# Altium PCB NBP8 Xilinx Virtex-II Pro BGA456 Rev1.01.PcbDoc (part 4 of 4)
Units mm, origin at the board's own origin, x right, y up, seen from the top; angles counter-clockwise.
Board outline 69 x 99.5 mm, 8 copper layers (Top Layer, InternalPlane1, InternalPlane2, MidLayer1, MidLayer2, MidLayer3, MidLayer4, Bottom Layer), stack 1.545 mm thick; 164 components, 314 nets, 1132 pads, 807 vias.
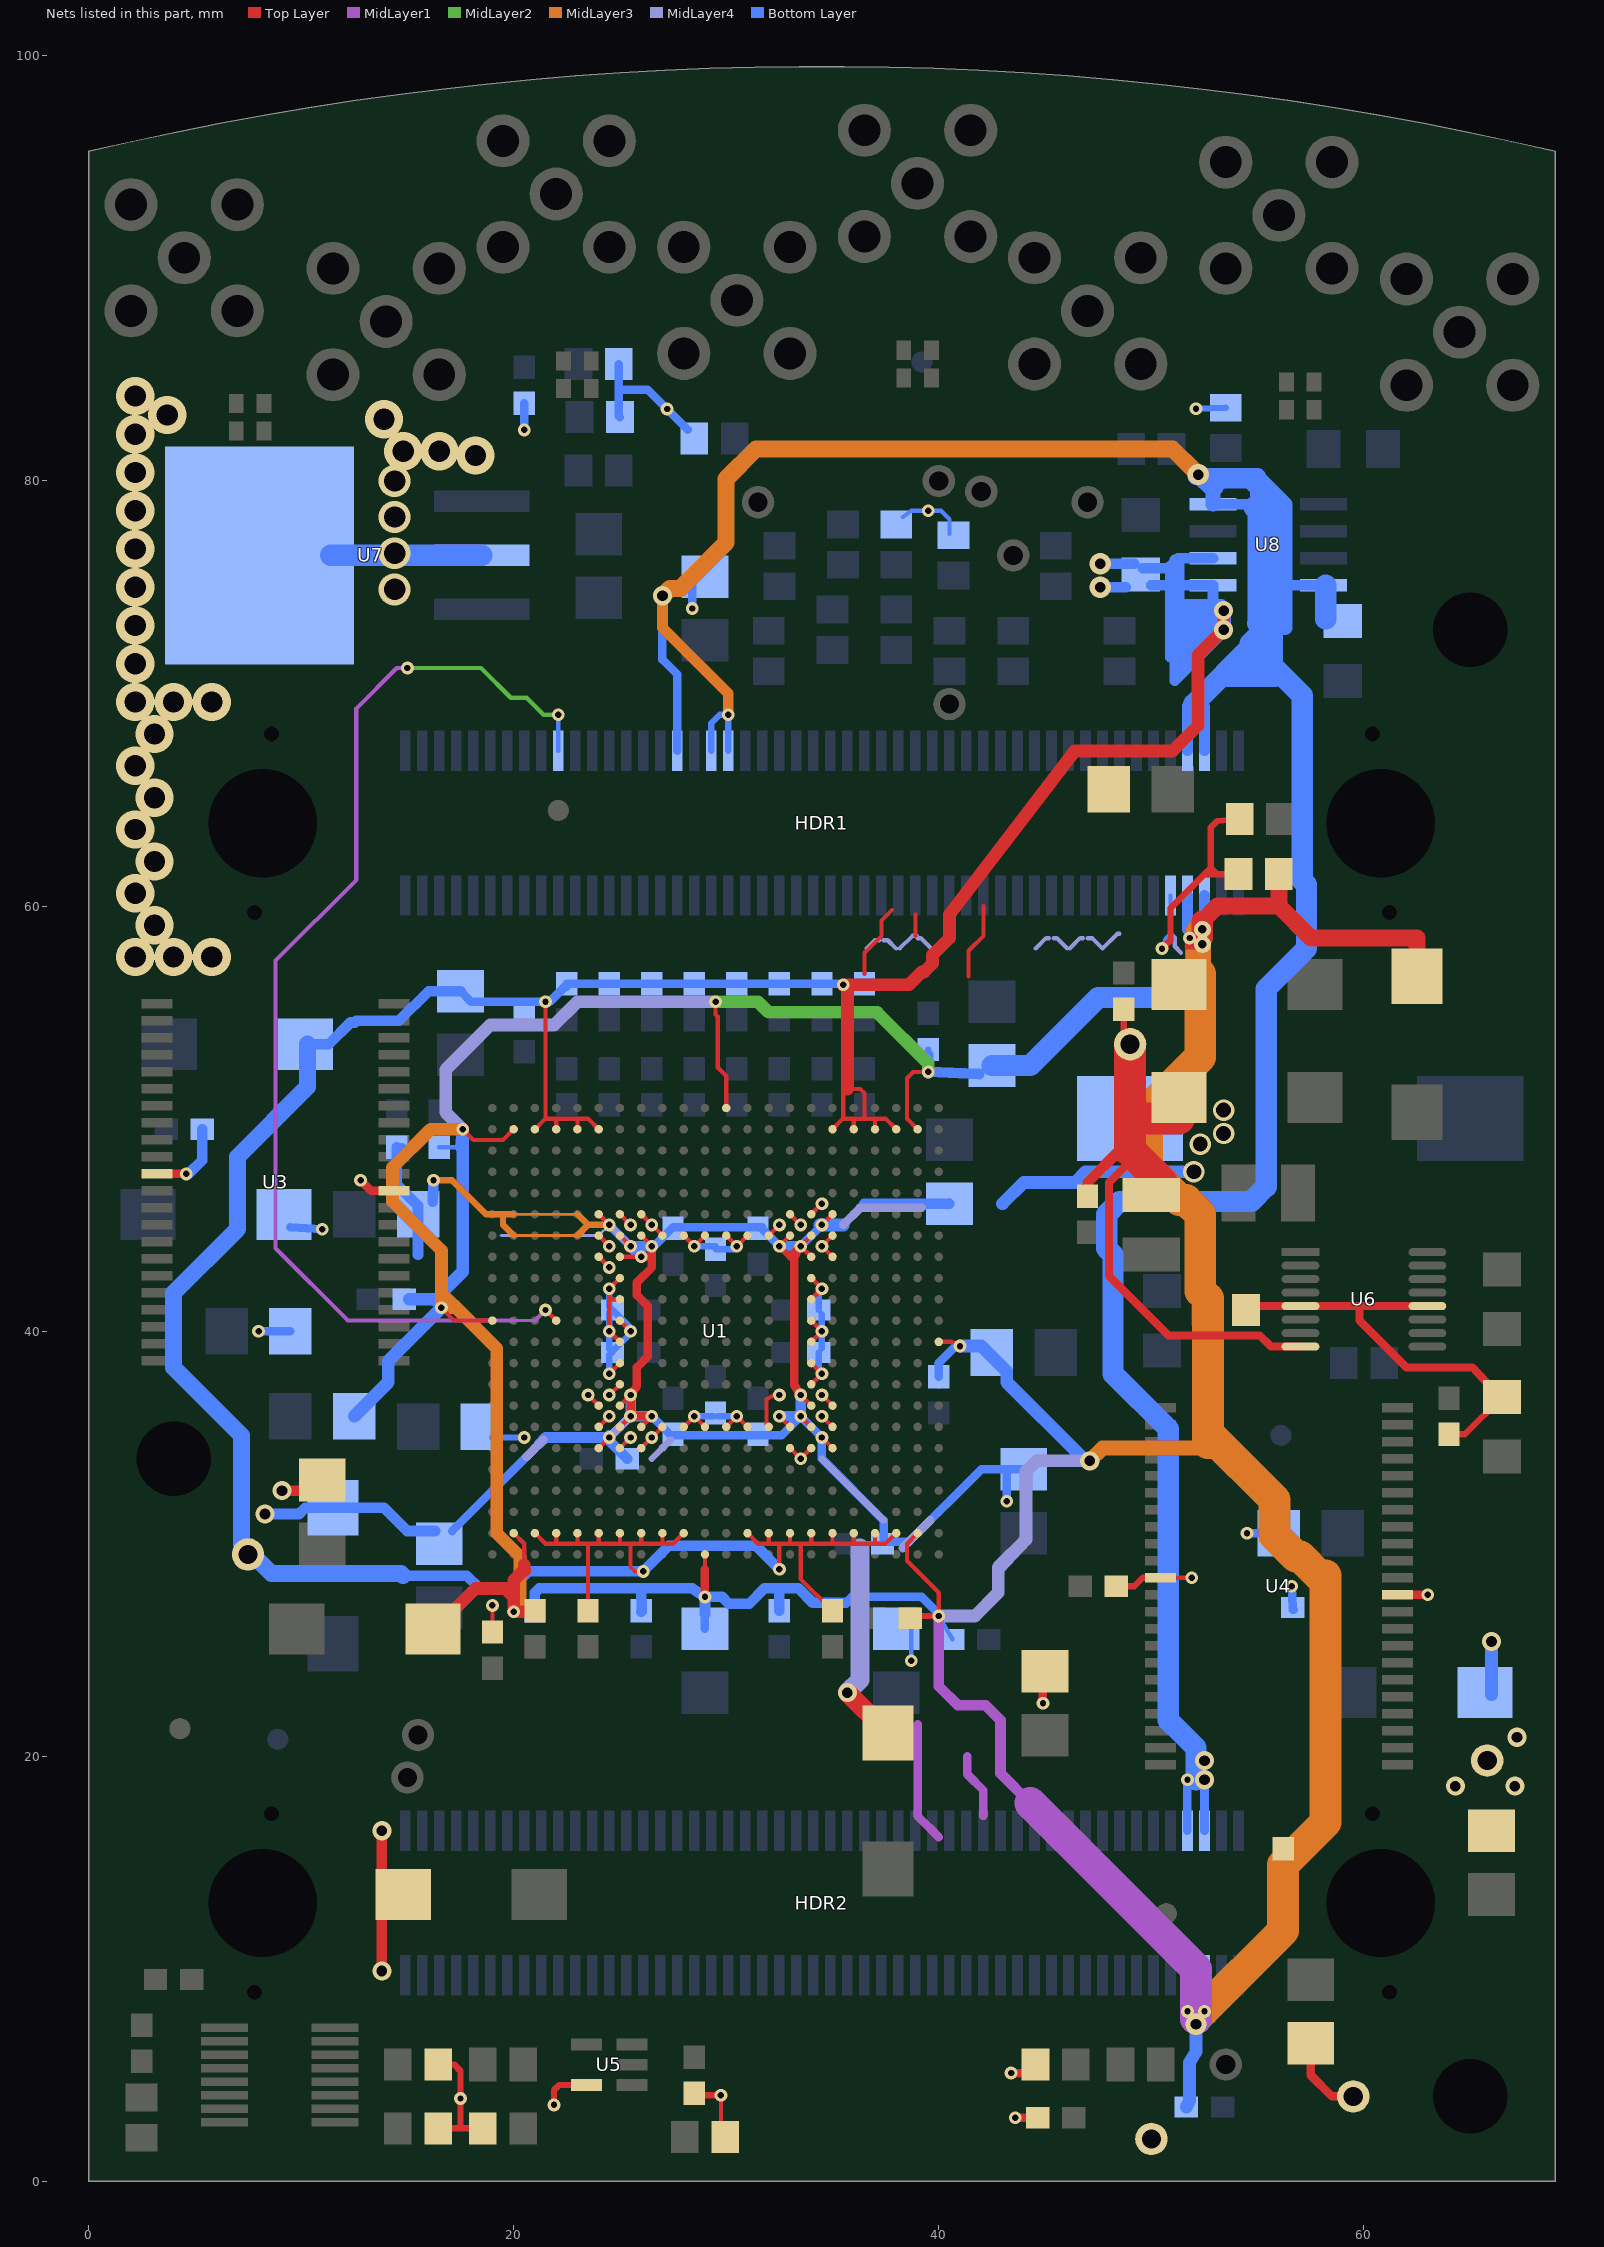
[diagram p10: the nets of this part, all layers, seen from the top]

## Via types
v1: diameter 0.6, hole 0.3, Top Layer to Bottom Layer, tented bottom, 695 vias
v2: diameter 0.9, hole 0.5, Top Layer to Bottom Layer, tented bottom, 45 vias
v3: diameter 1.8, hole 1, Top Layer to Bottom Layer, tented bottom, 26 vias
v4: diameter 1, hole 0.7, Top Layer to Bottom Layer, tented bottom, 17 vias
v5: diameter 1, hole 0.5, Top Layer to Bottom Layer, tented bottom, 15 vias
v6: diameter 1.5, hole 1, Top Layer to Bottom Layer, tented bottom, 4 vias
v7: diameter 0.8, hole 0.4, Top Layer to Bottom Layer, tented bottom, 3 vias
v8: diameter 0.9, hole 0.5, Top Layer to Bottom Layer, 2 vias

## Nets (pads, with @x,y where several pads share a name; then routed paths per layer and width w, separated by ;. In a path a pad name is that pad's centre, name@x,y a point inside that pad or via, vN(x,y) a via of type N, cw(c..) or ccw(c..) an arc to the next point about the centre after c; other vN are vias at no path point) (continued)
VCC: C9.1 C10.1 C11.1 C12.1 C13.1 C14.1 C15.1 C16.1 C17.1 C26.1 C27.1 C33.1 C35.1 C44.1 C45.1 C46.1 C47.1 C48.1 C49.1 C50.1 C56.1 C57.1 C58.1 C60.1 R10.1 R11.2 R12.1 R13.1 R14.2 R17.1 R19.2 R20.2 R23.1 R24.1 R27.2 TP11.1 U1.F7 U1.F8 U1.F15 U1.F16 U1.G6 U1.G9 U1.G10 U1.G11 U1.G12 U1.G13 U1.G14 U1.G17 U1.H6 U1.H17 U1.J7 U1.J16 U1.K7 U1.K16 U1.L7 U1.L16 U1.M7 U1.M16 U1.N7 U1.N16 U1.P7 U1.P16 U1.R6 U1.R17 U1.T6 U1.T9 U1.T10 U1.T11 U1.T12 U1.T13 U1.T14 U1.T17 U1.U7 U1.U8 U1.U15 U1.U16 U3.11 U3.33 U4.11 U4.33 U5.5 U7.2 U7.4 | length 118.6
  Top Layer w0.2: C33.1@19,25.85 v1(19,27.1) ; v1(23.5,37) U1.H17@24,36.5 ; U1.G17@24,35.5 v1(24.5,36) ; U1.R17@24,43.5 v1(24.5,43) ; U1.T17@24,44.5 v1(24.5,44) ; v1(24.5,37) U1.J16@25,37.5 ; v1(24.5,38) U1.K16@25,38.5 ; U1.L16@24.9,39.6 v1(24.5,40) 24.5,41.5 ; U1.F16@25,34.5 v1(25.5,35) ; U1.M16@25,40.4 25.1,40.4 v1(25.5,40) ; U1.N16@25,41.5 24.5,41.5 ; U1.P16@25,42.5 v1(24.5,42) 24.5,41.5 ; U1.U16@25,45.5 v1(25.5,45) ; U1.F15@26,34.5 v1(26.5,35) U1.G14@27,35.5 ; U1.U15@26,45.5 v1(26.5,45) U1.T14@27,44.5 ; U1.T13@28,44.5 v1(28.5,44) U1.T12@29,44.5 ; U1.G13@28.1,35.5 28.1,35.6 v1(28.5,36) U1.G12@29,35.5 ; R14.2@29.75,2.15 v1(29.75,4.05) ; U1.G11@30,35.5 v1(30.5,36) U1.G10@31,35.5 ; U1.T11@30,44.5 v1(30.5,44) U1.T10@31,44.5 ; U1.G9@32,35.5 31.9,35.6 31.9,36.8 32.25,37 v1(32.5,37) ; U1.T9@32,44.5 v1(32.5,45) ; U1.F8@33,34.5 v1(33.5,34) U1.F7@34,34.5 ; U1.U8@33,45.5 v1(33.5,45) ; U1.J7@34,37.5 v1(34.5,38) U1.K7@34,38.5 ; U1.L7@34,39.5 v1(34.5,40) U1.M7@34,40.5 ; U1.N7@34,41.5 v1(34.5,42) U1.P7@34,42.5 ; U1.U7@34,45.5 v1(34.5,46) ; v1(34.5,36) U1.G6@35,35.5 ; v1(34.5,37) U1.H6@35,36.5 ; U1.R6@35,43.5 v1(34.5,44) U1.T6@35,44.5 ; C44.1@44.9,24 44.95,24.05 C44.1@45,24.1 ; U4.11@50.5,28.4 v1(51.9,28.4)
  Top Layer w0.3: R17.1@16.45,2.5 17.5,2.5 ; R10.1@16.45,5.5 17.2,5.5 17.5,5.2 v1(17.5,3.9) 17.5,2.5 ; R20.2@18.55,2.5 17.5,2.5 ; v1(21.9,3.6) 21.9,4.3 22.141,4.541 U5.5@23.42,4.541 ; C35.1@28.5,4.05 v1(29.75,4.05) ; C27.1@48.35,28 49.2,28 49.6,28.4 U4.11@50.425,28.4
  Top Layer w0.4: U3.11@2.925,47.4 U3.11@3.225,47.4 4.4,47.4 v1(4.6,47.4) ; v1(12.8,47.1) 13.3,46.6 U3.33@14.375,46.6 U3.33@14.9,46.6 ; v1(43.4,5.1) 44.4,5.1 44.6,5.3 R19.2@44.6,5.5 ; v1(43.6,3) C13.1@44.65,3 C13.1@44.7,3 ; v1(44.9,22.5) C44.1@44.9,24 ; C60.1@57.5,6.5 57.5,5 58.5,4 TP11.1@59.5,4 ; U4.33@61.575,27.6 v1(63,27.6)
  Top Layer w0.5: v2(9.1,32.5) C46.1@11,32.5 ; v8(13.8,9.9) v8(13.8,16.5)
  Bottom Layer w0.2: R11.2@38.3,78.3 38.7,78.6 v1(39.5,78.6) 40.1,78.6 40.5,78.2 R13.1@40.5,77.5 ; v1(38.7,24.5) C48.1@38.7,26
  Bottom Layer w0.3: C50.1@19,35 v1(20.5,35) ; v1(24.5,38) 24.5,38.9 24.6,39 C14.1@24.65,39 24.5,39.15 v1(24.5,40) 24.5,40.9 24.6,41 C11.1@24.65,41 ; v1(24.5,42) 24.5,41.15 C11.1@24.65,41 ; C14.1@24.7,39.1 25.5,39.9 v1(25.5,40) 25.5,40.15 C11.1@24.65,41 ; v1(28.5,36) C12.1@29.4,36 ; v1(28.5,44) C10.1@29.5,44 ; C10.1@29.5,43.85 30.35,43.85 v1(30.5,44) ; C12.1@29.6,36 v1(30.5,36) ; C9.1@34.35,39 34.35,38.15 v1(34.5,38) ; C16.1@34.35,41 34.35,41.85 v1(34.5,42) ; C9.1@34.5,39.2 v1(34.5,40) C16.1@34.5,40.8 ; v1(52.1,83.4) R27.2@53.5,83.45
  Bottom Layer w0.4: v1(8,40) C47.1@9.5,40 ; C56.1@9.5,44.9 v1(11,44.8) ; v1(20.5,82.4) C17.1@20.5,83.65 ; R23.1@24.95,85.5 24.95,84.3 ; R24.1@25,83 24.95,83.05 24.95,84.3 ; R12.1@28.2,82.4 v1(27.218,83.382) 26.3,84.3 24.95,84.3 ; v1(28.4,74) C45.1@28.4,75.5 ; v1(54.5,30.5) C49.1@56,30.5 ; v1(56.6,28) 56.645,27 56.65,26.9 C15.1@56.7,26.9
  Bottom Layer w0.5: v1(4.6,47.4) 4.7,47.4 5.35,48.05 C26.1@5.35,49.5
  Bottom Layer w0.6: v2(66,25.4) 66,23 C57.1@66,22.9
  Bottom Layer w1: U7.4@11.4,76.5 14.4,76.5 U7.2@18.5,76.5
  other v3: 2.2,57.6 4,57.6 5.8,57.6 3.1,59.1 2.2,60.6 3.1,62.1 2.2,63.6 3.1,65.1 2.2,66.6 3.1,68.1 2.2,69.6 4,69.6 5.8,69.6 2.2,71.4 2.2,73.2 2.2,75 2.2,76.8 2.2,78.6 2.2,80.4 18.2,81.2 14.8,81.4 16.5,81.4 2.2,82.2 13.9,82.9 3.7,83.1 2.2,84
  other v6: 14.4,74.9 14.4,76.6 14.4,78.3 14.4,80
VCCAUX: C1.1 C2.1 C3.1 C4.1 C5.1 C6.1 C7.1 C28.1 C29.1 C30.1 C31.1 C36.1 C37.1 C38.1 C39.1 C51.1 C52.1 HDR1.93 HDR1.95 HDR2.93 HDR2.95 R15.1 TP14.1 U1.A12 U1.AA2 U1.AA21 U1.AB11 U1.B2 U1.B21 U1.L1 U1.M22 | length 312.9
  Top Layer w0.2: v1(16.6,41.1) 17.2,40.5 U1.M22@19,40.5 ; v1(17.6,49.5) 18.1,49 19.5,49 U1.AA21@20,49.5 ; 20,27.9 20,28.271 20,28.5 20.5,29 20.5,30 U1.B21@20,30.5 ; 29,28.8 U1.A12@29,29.5 ; v1(29.5,55.5) 29.5,54.9 29.6,54.8 29.6,52.4 30,52 U1.AB11@30,50.5 ; U1.B2@39,30.5 38.5,30 38.5,29.2 40,27.7 v1(40,26.6) ; U1.AA2@39,49.5 38.5,50 38.5,51.9 38.8,52.2 v1(39.5,52.2) ; U1.L1@40,39.5 40.6,39.5 v1@41,39.4
  Top Layer w0.3: C31.1@38.9,26.6 v1(40,26.6) ; 51.7,58.1 51.8,58.1 v7@52.4,58.1
  Top Layer w0.4: v1(29,27.5) 29,28.8
  Top Layer w0.6: C51.1@16.2,26 16.3,26 18.2,27.9 19.6,27.9 ; 20.5,29 20.5,28.771 ; 20.529,28.771 20.5,28.771 ; C30.1@20.7,26.8 v1(20,26.8) 20,27.5 ; 19.6,27.9 20,27.5 ; 19.6,27.9 20,27.9 ; 20,27.5 20,27.9 ; 20,27.9 20,28.271 20.5,28.771
  Top Layer w0.8: v7@52.4,59.3 53.1,60 56,60 ; R15.1@56,61.5 56,60 ; C52.1@62.5,56.7 62.5,58.5 57.5,58.5 56,60
  Top Layer w1: v7@52.4,58.5 v7(52.4,58.9) v7@52.4,59.3
  MidLayer1 w0.4: 39,21.5 39,17.2 40,16.2 ; 41.342,20 41.342,19.158 42.1,18.4 42.1,17.2
  MidLayer1 w0.5: v1(40,26.6) 40,23.3 40.9,22.4 42.2,22.4 42.9,21.7 42.9,19.2 44.3,17.8
  MidLayer1 w1.5: 44.3,17.8 52.1,10 52.1,8 v5@52.1,7.663
  MidLayer2 w0.6: v1(29.5,55.5) 31.5,55.5 32,55 37.1,55 39.5,52.6 v1(39.5,52.2)
  MidLayer3 w0.6: v1(17.6,49.5) 16.1,49.5 14.3,47.7 14.3,46.1 16.6,43.8 16.6,41.8 ; v1(20,26.8) 20.3,27.1 20.3,29.4 19.2,30.5 19.2,39.2 17.3,41.1 ; 16.6,41.8 v1(16.6,41.1) 17.3,41.1 ; 16.6,41.8 16.95,41.45 17.3,41.1
  MidLayer3 w0.7: v2(47.1,33.9) 47.7,34.5 52.3,34.5
  MidLayer3 w1.2: v7@52.2,58.8 52.2,58.5 52.2,58.2 52.2,56.9 52.3,56.8
  MidLayer3 w1.5: v5@52.1,7.7 52.45,8.05 56.2,11.8 56.2,14.9 58.2,16.9 58.2,28.5 57.9,28.5 57,29.4 56.8,29.4 55.8,30.4 55.8,32.069 52.669,35.2 ; 52.3,56.8 52.3,52.9 49.8,50.4 49.8,47.7 51.325,46.175 51.625,46.175 52.3,45.5 52.3,41.9 52.669,41.531 52.669,35.2 ; 52.669,34.731 52.669,35.2
  MidLayer4 w0.6: v1(17.6,49.5) 16.8,50.3 16.8,52.3 18.9,54.4 21.9,54.4 23,55.5 v1(29.5,55.5) ; v1(40,26.6) 41.7,26.6 42.8,27.7 42.8,28.8 44.1,30.2 ; 42.8,28.9 44.1,30.2 ; v2(47.1,33.9) 44.6,33.9 44.1,33.4 44.1,30.2
  Bottom Layer w0.2: C4.1@16.5,48.65 17.35,48.65 17.563,48.863 17.6,48.9 v1(17.6,49.5) v1@17.6,49.6 ; v1(20,26.8) 20.95,26.8 C1.1@21,26.85 ; v1(40,26.6) C2.1@40.65,25.5 ; HDR2.93@51.7,9.6 HDR2.93@51.7,9.7
  Bottom Layer w0.3: v1(39.5,52.2) C5.1@39.5,53.25
  Bottom Layer w0.38: C29.1@15.1,41.5 16.1,41.5 v1(16.6,41.1) ; v1(41,39.3) C39.1@41.8,39.3
  Bottom Layer w0.4: C37.1@29,26 v1(29,27.5) ; 35.617,27.217 35.9,27.5 39.2,27.5 40,26.7 v1(40,26.6) ; C7.1@40,37.85 40,38.5 40.8,39.3 v1(41,39.3) ; HDR2.93@51.7,9.6 v1(51.7,8) ; HDR2.95@52.5,9.7 v1(52.5,8) ; v1(51.7,8) 52.1,8 v1(52.5,8) ; v1(51.7,8) 51.7,7.8 v5(52.1,7.4) 52.5,7.8 v1(52.5,8)
  Bottom Layer w0.5: v1(20,26.8) 20.05,26.85 C1.1@21,26.85 21,27.7 21.2,27.9 26,27.9 ; C3.1@26,26.8 26.025,26.825 26.024,26.851 26,27.9 ; C37.1@29,26.7 v1(29,27.5) ; C6.1@32.5,26.85 32.5,27.9 ; 35.617,27.217 34.083,27.217 33.4,27.9 32.5,27.9 ; C5.1@39.5,53 v1(39.5,52.2) C38.1@41.9,52.1 ; 51.7,58.9 HDR1.93@51.7,60.5 ; v7@52.5,58.9 HDR1.95@52.5,60.5 ; 26,27.9 28.4,27.9 v1(29,27.5) ; v1(29,27.5) 29.8,27.5 30.114,27.186 31.086,27.186 31.8,27.9 32.5,27.9
  Bottom Layer w0.6: C36.1@12.5,36 14.1,37.6 14.1,38.6 v1(16.6,41.1) 16.6,41.5 ; C29.1@15.1,41.5 16.1,41.5 16.6,41.5 ; 17.55,48.65 17.563,48.863 v1(17.6,49.5) 17.6,48.9 17.6,42.8 16.6,41.8 16.6,41.5 ; v1(41,39.3) 42,39.3 42.4,38.9 43.2,38.1 43.2,37.6 46.7,34.1 v2(47.1,33.9) ; C28.1@51.65,3.5 51.8,3.8 51.8,5.6 52.1,6.1 v5(52.1,7.4)
  Bottom Layer w1: C38.1@42.5,52.5 44.3,52.5 47.5,55.7 50.9,55.7 52.1,56.9 52.1,58.2 v1@52.1,58.5
  other v1: 51.8,58.5
  other v7: 52.4,58.2
VCCIN: C76.1 C88.1 C93.2 HDR1.34 HDR1.38 HDR1.40 HDR1.94 HDR1.96 HDR2.94 HDR2.96 TP13.1 U8.4 U8.8 | length 182.7
  MidLayer3 w0.5: v2(27,74.6) 27,73.1 30.1,70 v1(30.1,69)
  MidLayer3 w0.8: v2(27,74.6) 27.351,74.951 27.851,74.951 30,77.1 30,80.1 31.4,81.5 51,81.5 v5@52,80.5
  Bottom Layer w0.3: HDR1.38@29.3,67.3 29.3,68.6 29.7,69 v1(30.1,69) HDR1.40@30.1,67.3 ; v1(51.7,18.9) 52.1,18.9 v2(52.5,18.9)
  Bottom Layer w0.4: v2(27,74.6) 27,71.6 27.7,70.9 HDR1.34@27.7,67.3 ; HDR2.94@51.7,16.5 v1(51.7,18.9) ; HDR2.96@52.5,16.5 v2(52.5,18.9)
  Bottom Layer w0.5: HDR1.94@51.7,67.3 51.7,69.4 52.089,69.789 ; HDR1.96@52.5,67.3 52.5,69.377 52.189,69.689 52.089,69.789 ; U8.8@52.9,78.905 54.695,78.905 55.5,78.1 55.5,74.1 55.5,73.2 54.653,72.353 52.089,69.789 ; 55.6,74.7 55.7,74.8 55.9,75 55.9,75.095 ; 55.6,75.6 55.7,75.5 56,75.2 ; 55.805,75.095 55.9,75.095 ; U8.4@58.2,75.095 U8.4@58.1,75.095 56.3,75.095 55.9,75.095
  Bottom Layer w0.7: U8.8@52.9,78.905 52.9,79.6 53,79.7 53.3,80 54.6,80 55,79.6 ; 54.4,80.2 55,80.2 56.3,78.9 56.3,78.2 ; 55,78.7 55,79.5 ; 55,80 55,79.6 ; 56.3,73.1 56.3,75.095 56.3,78.2 ; 55,79.5 55,79.6 ; 55,79.5 56.3,78.2
  Bottom Layer w0.8: v5@52.1,80.2 52.2,80.2 v5@52.3,80.2 ; v5(52.2,80.3) v5@52.3,80.2 ; 55,80.2 v5@52.5,80.2 ; v5@52.3,80.2 52.8,79.7 53,79.7 v5@52.5,80.2 ; v5@52.3,80.2 v5@52.5,80.2
  Bottom Layer w1: 52,69.5 52.189,69.689 54.653,72.153 54.653,72.353 57.1,69.905 57.1,61.2 57.3,61 57.3,58 55.4,56.1 55.4,46.8 54.7,46.1 48.5,46.1 47.9,45.5 47.9,43.9 48.2,43.6 48.2,38 50.8,35.4 50.8,21.7 52.1,20.4 52.1,19.8 v2@52.1,18.9 ; 53.6,70.8 55.8,70.8 55.2,71.4 54.5,71.4 ; 54.741,72.441 55.5,73.2 55.7,73.4 ; 54.836,78.764 55.5,78.1 55.7,77.9 55.7,75.5 55.7,74.8 55.7,73.4 ; 55,73.3 55.013,73.313 55.013,73.713 ; 55.013,78.587 55.013,73.713 ; 55.5,74.1 55.4,74.1 55.013,73.713 ; 55.7,71.459 55.7,73.4 ; C93.2@58.2,73.5 U8.4@58.2,75.095
  other v2: 64.3,18.6 67.1,18.6 52.5,19.8 67.2,20.9
VCCINT: C18.1 C19.1 C20.1 C21.1 C22.1 C23.1 C24.1 C25.1 C34.1 C40.1 C41.1 C42.1 C43.1 C53.1 C54.1 C55.1 C61.1 C62.2 L1.2 TP10.1 U1.F6 U1.F17 U1.G7 U1.G8 U1.G15 U1.G16 U1.H7 U1.H16 U1.R7 U1.R16 U1.T7 U1.T8 U1.T15 U1.T16 U1.U6 U1.U17 U6.8 | length 207.5
  Top Layer w0.2: U1.F17@24,34.5 v1(24.5,35) ; U1.U17@24,45.5 v1(24.5,45) ; U1.H16@25,36.5 v1(25.5,37) ; U1.R16@25,43.5 v1(26,43.5) ; U1.T16@25,44.5 v1(25.5,44) ; U1.G16@25.1,35.5 U1.G16@25,35.5 v1(25.5,36) ; U1.G15@26,35.5 v1(26.5,36) ; U1.T15@26,44.5 v1(26.5,44) ; v1(32.5,36) U1.G8@33,35.5 ; v1(32.5,44) U1.T8@33,44.5 ; v1(33.5,36) U1.G7@34,35.5 ; v1(33.5,37) U1.H7@34,36.5 ; U1.R7@34,43.5 v1(33.5,44) U1.T7@34,44.5 ; v1(34.5,35) U1.F6@35,34.5 ; v1(34.5,45) U1.U6@35,45.5 ; 55.6,39.3 55.622,39.278
  Top Layer w0.3: v1(32.5,44) 32.984,43.516 ; 32.984,43.484 32.984,43.516 ; C22.1@48.7,55.15 48.7,53.9 TP10.1@49,53.5 ; 32.984,43.516 33.468,44 v1(33.5,44) 33.2,43.3 32.984,43.516
  Top Layer w0.38: 48.8,47.8 48,47 48,42.6 50.8,39.8 55.1,39.8 55.6,39.3 ; 55.622,39.278 U6.8@57.015,39.278
  Top Layer w0.4: v1(26,43.5) 26.5,43.5 ; v1(26.5,36) v1(25.5,36) v1(25.5,37) 25.8,37.4 25.8,38.3 26.3,38.8 26.3,41.2 25.8,41.7 25.8,42.3 26.5,43 26.5,43.5 ; v1(26.5,44) 26.5,43.5 ; v1(33.5,37) 33.2,37.468 33.2,43.3 33.2,43.7 v1(33.5,44)
  Top Layer w0.5: C25.1@47,46.35 47,47 48.5,48.5
  Top Layer w0.9: v2(35.7,23) 37.5,21.2 37.5,21.1 C53.1@37.5,21
  Top Layer w1.5: TP10.1@49,53.5 49,50.5 ; C62.2@50.5,46.5 50.5,47 49,48.5 49,50.5 ; C61.1@51.3,50 49.5,50 49,50.5
  MidLayer3 w0.127: 20,44.5 23,44.5 ; 20,45.5 23,45.5
  MidLayer3 w0.3: v1(16.229,47.1) 17.1,47.1 18.7,45.5 19.5,45.5 ; 20,44.5 19.5,45 19.5,45.5 ; 20,45.5 19.5,45.5 ; 23,44.5 23.5,45 ; 23,45.5 23.5,45 ; v1(24.5,45) 23.5,45
  MidLayer4 w0.127: 19.4,44.5 23.4,44.5 24,44.5 v1(24.5,45) 23.474,45 22.974,45.5 19.4,45.5
  MidLayer4 w0.2: 21.403,34.811 21.403,34.903 21.408,34.908 ; 36.5,30 37.5,30 ; 36.607,58 37.001,58.394 37.2,58.394 ; 37.4,58.394 37.599,58.394 37.993,58 ; 38.158,58 38.758,58.6 38.958,58.6 ; 39.012,58.492 39.149,58.492 39.642,58 ; 44.558,58 45.051,58.492 45.188,58.492 ; 45.412,58.492 45.549,58.492 46.042,58 ; 46.158,58 46.651,58.492 46.788,58.492 ; 47.012,58.492 47.214,58.492 47.706,58 48.407,58.7 48.5,58.7 ; 51,58.625 51.1,58.524 51.1,58.107 51.4,57.807
  MidLayer4 w0.3: v1(24.5,45) v1(25.5,44) ; 26.499,34.001 27.401,34.903 ; 34.5,34 37.403,31.097
  MidLayer4 w0.4: 20.597,34.097 21.403,34.903 ; v1(24.5,35) v1(25.5,36) ; 35.5,45 36.265,45.764 ; 36.275,45.8 39.2,45.8 ; 38.3,29.8 39.6,31.1
  MidLayer4 w0.9: v2(35.7,23) 36.3,23.6 36.3,29.8
  Bottom Layer w0.3: v1(26.5,44) v1@26.6,44
  Bottom Layer w0.4: C34.1@14.5,48.65 C34.1@14.75,48.65 ; C42.1@17.1,30.6 21.2,34.7 ; v1(24.5,35) v1(25.5,36) ; v1(24.5,45) v1(25.5,44) ; v1(26.5,36) 27.4,35.1 27.5,35.1 31.5,35.1 32.6,35.1 v1(33.5,36) v1(34.5,35) 34.5,34 37.4,31.1 37.4,30.1 38.6,30.1 42,33.5 C40.1@44,33.5 ; v1@26.6,44 27.475,44.875 27.5,44.9 31.5,44.9 C18.1@31.6,44.9 ; C18.1@31.7,44.9 C18.1@31.6,44.9 ; v1(32.5,44) C18.1@31.6,44.9 ; v1(33.5,44) v1(34.5,45) 35.5,45 36.5,46 ; C43.1@40.487,46.072 C43.1@40.499,46.072 ; v1(43.2,32) C40.1@43.2,33.4
  Bottom Layer w0.5: v2(8.3,31.4) 9.9,31.4 10.2,31.7 C54.1@11.5,31.7 13.9,31.7 15,30.6 C42.1@16.3,30.6 ; C34.1@14.5,48.65 14.5,46.9 15.5,45.9 C41.1@15.5,45.5 15.5,43.6 ; C41.1@16.2,46.1 v1(16.229,47.1) ; 21.2,34.7 21.5,35 24.4,35 24.45,35.05 24.5,35.1 v1(24.5,35) 24.5,34.85 C24.1@25.35,34 ; v1(25.5,37) v1(25.5,36) v1(26.5,36) ; v1(26,43.5) v1(25.5,44) 26,44 v1(26.5,44) ; v1(32.5,36) v1(33.5,36) v1(33.5,37) ; v1(32.5,44) v1(33.5,44) ; 36.5,46 C43.1@40.5,46
  Bottom Layer w0.6: v1@34.4,45 v1(34.5,45) 35.5,45 ; 43,46 44,47 46.4,47 46.9,47.5 v4(52,47.5)
  other v4: 52.3,48.8 53.4,49.3 53.4,50.4
VCCRIO: C77.1 C78.1 C79.1 C89.1 C90.1 C91.1 C92.2 L2.2 L3.2 L4.2 L5.2 L6.2 L7.2 L8.2 L9.2 TP12.1 U1.AA3 U1.AA4 U1.AA5 U1.AA6 U1.AA17 U1.AA18 U1.AA19 U1.AA20 U1.B3 U1.B4 U1.B5 U1.B6 U1.B7 U1.B8 U1.B9 U1.B10 U1.B13 U1.B14 U1.B15 U1.B16 U1.B17 U1.B18 U1.B19 U1.B20 U8.5 U8.6 | length 223.1
  Top Layer w0.2: U1.B20@21,30.5 21.5,30 23.5,30 ; U1.AA20@21,49.5 21.5,50 ; v1(21.5,55.5) 21.5,50 ; 22,30 U1.B19@22,30.5 ; U1.AA19@22,49.5 22,50 ; 23,30 U1.B18@23,30.5 ; U1.AA18@23,49.5 23,50 ; C78.1@23.5,26.85 23.5,30 ; 24,30 U1.B17@24,30.5 ; U1.AA17@24,49.5 23.5,50 23,50 ; 25,30 U1.B16@25,30.5 ; 26,30 U1.B15@26,30.5 ; v1(26.1,28.7) 25.7,28.7 25.5,28.9 25.5,30 ; 27,30 U1.B14@27,30.5 ; U1.B13@28,30.5 27.5,30 25.5,30 ; U1.B10@31,30.5 31.5,30 32,30 ; U1.B9@32,30.5 32,30 ; v1(32.5,28.8) 32.5,30 ; U1.B8@33,30.5 33,30 ; U1.B7@34,30.5 34,30 ; C79.1@35,26.85 33.5,28.35 33.5,30 ; U1.B6@35,30.5 35,30 ; U1.AA6@35,49.5 35.5,50 ; v1(35.5,56.3) 35.5,51.4 ; 36,30 U1.B5@36,30.5 ; U1.AA5@36,49.5 36,50 ; 36.5,56.8 36.5,57.8 37.3,58.6 37.3,59.317 37.8,59.817 ; 37,30 U1.B4@37,30.5 ; U1.AA4@37,49.5 37,50 ; U1.B3@38,30.5 37.5,30 35,30 ; U1.AA3@38,49.5 37.5,50 37,50 ; 38.9,58.6 38.9,59.6 ; 41.4,56.7 41.4,57.9 42.1,58.6 42.1,60 ; 21.5,50 23,50 ; 23.5,30 25.5,30 ; 32,30 32.5,30 ; 32.5,30 33,30 ; 33,30 33.5,30 ; 33.5,30 34,30 ; 34,30 35,30 ; 35.5,50 36,50 ; 35.5,50 35.5,51.4 ; 35.5,51.4 35.7,51.4 36.3,51.4 36.5,51.2 36.5,50 ; 36,50 36.5,50 ; 36.5,50 37,50
  Top Layer w0.6: 35.7,51.4 35.7,56.1 v1(35.5,56.3) 38.6,56.3 39.2,56.9 39.3,56.9 39.7,57.3 39.7,57.7 40.5,58.5 40.5,59.6 46.4,67.3 51,67.3 52.2,68.5 52.2,71.8 v2(53.4,73) v2(53.4,73.9)
  Bottom Layer w0.4: C89.1@17.5,56 18,55.5 20.5,55.5 v1(21.5,55.5) 21.7,55.5 L2.2@22.5,56.3 ; L2.2@22.5,56.2 L2.2@22.5,56.3 ; L8.2@36.5,56.35 35.5,56.35 L9.2@34.5,56.35 L7.2@32.5,56.35 L6.2@30.5,56.35 L4.2@28.5,56.35 L5.2@26.5,56.35 L3.2@24.5,56.35 L2.2@22.5,56.35 L2.2@22.5,56.3
  Bottom Layer w0.5: C91.1@10.2,53.5 10.3,53.5 11.3,53.5 12.323,54.523 12.523,54.523 12.6,54.6 14.6,54.6 16,56 C89.1@17.5,56 ; 14.8,28.5 17.8,28.5 18.4,27.9 19.9,27.9 20.7,28.7 v1(26.1,28.7) 27.3,29.9 31.4,29.9 v1(32.5,28.8) ; v5(47.6,75) C92.2@48.8,75 ; v5(47.6,76.1) C92.2@49.2,76.1 ; C92.2@49.6,75.9 50.8,75.9 50.9,76 ; C92.2@50,75.1 50.005,75.095 50.9,75.095 ; 51.1,76.3 51.1,76.2 ; U8.6@52.9,76.365 51.265,76.365 51.1,76.2 ; 50.9,75.095 50.9,71.7 51.1,71.9 ; 50.9,75.095 50.9,76 ; 50.9,75.095 51.1,75.095 ; 50.9,76 51,76.1 ; 51,76.1 51.1,76.1 ; 51,76.1 51.1,76.2 ; 51.1,71.9 51.4,72.2 ; 51.1,71.9 51.1,70.6 53.45,72.95 53.5,73 53.5,73.9 53.5,74 53.3,74.2 52.9,74.2 ; 51.1,71.9 51.1,73.9 ; 51.1,73.9 51.25,74.05 ; 51.1,73.9 51.1,74.2 ; 51.1,74.2 51.25,74.05 ; 51.1,74.2 51.1,75.095 ; 51.1,74.2 51.3,74.2 ; 51.1,75.095 51.1,76.1 ; 51.1,75.095 51.3,75.095 ; 51.1,76.1 51.1,76.2 ; 51.1,76.1 51.3,76.1 51.3,75.095 ; 51.25,74.05 51.3,74.1 51.3,74.2 ; 51.25,74.05 51.4,73.9 51.4,72.2 ; 51.3,74.2 51.3,75.095 ; 51.3,74.2 52.9,74.2 ; 51.3,75.095 U8.5@52.9,75.095 52.9,74.2 ; 51.4,72.2 51.7,72.5 ; 51.4,72.2 51.4,71.4 53,73 53,73.9 52.9,73.8 52.7,73.8 ; 51.7,72.5 51.9,72.7 51.9,73 ; 51.7,72.5 51.7,72.2 52.6,73.1 52.6,73.5 52.4,73.5 51.9,73 ; 51.7,72.5 51.7,73.7 51.6,73.8 51.9,73.8 ; 51.9,73 51.9,73.8 ; 51.9,73.8 52.7,73.8 ; 52.7,73.8 52.9,74 52.9,74.2
  Bottom Layer w0.8: C91.1@10.3,53.5 10.3,51.5 7,48.2 7,44.8 4,41.8 4,38.3 7.2,35.1 7.2,30 7.6,29.6 8.6,28.6 14.7,28.6 14.8,28.5
VDRIVE: HDR1.20 U1.M19 | length 54.9
  Top Layer w0.2: v1(21.5,41) U1.M19@22,40.5
  MidLayer1 w0.127: 20,40.5 21,40.5
  MidLayer1 w0.2: v1(15,71.2) 14.5,71.2 12.6,69.3 12.6,61.234 8.8,57.434 8.8,43.9 12.2,40.5 20,40.5 ; 21,40.5 v1(21.5,41)
  MidLayer2 w0.2: v1(15,71.2) 18.466,71.2 19.866,69.8 20.6,69.8 21.4,69 v1(22.1,69)
  Bottom Layer w0.2: HDR1.20@22.1,67.3 v1(22.1,69)
VFILT: C64.1 C65.2 R21.1 U6.5 U6.12 | length 20.4
  Top Layer w0.3: C64.1@64,35.15 64.75,35.15 C65.2@66.5,36.9
  Top Layer w0.38: R21.1@54.517,41.183 U6.5@57.015,41.183 59.8,41.183 ; U6.12@62.385,41.183 59.8,41.183 ; C65.2@66,37 C65.2@66.3,37 ; C65.2@66.6,37 66.5,37 C65.2@66.3,37 ; 59.8,41.183 59.8,40.5 62,38.3 65.1,38.3 C65.2@66.3,37
VREF: HDR1.91 R15.2 R16.1 | length 13.1
  Top Layer w0.3: v1(50.5,58) 50.9,58.4 50.9,59.9 52.5,61.5 ; R15.2@54.1,61.5 53.1,61.5 ; R16.1@54.15,64.1 53.1,64 52.8,63.7 52.8,61.8 ; 52.5,61.5 52.8,61.8 ; 52.5,61.5 52.8,61.5 ; 52.8,61.5 53.1,61.5 ; 52.8,61.5 52.8,61.8 ; 52.8,61.8 53.1,61.5
  Bottom Layer w0.2: v1(50.5,58) 50.7,58.5 50.9,58.7 HDR1.91@50.9,60.5
pads on no net: HDR1.MH1 HDR1.MH2 HDR1.MH3 HDR1.MH4 HDR1.MH5 HDR1.MH6 HDR2.MH1 HDR2.MH2 HDR2.MH3 HDR2.MH4 HDR2.MH5 HDR2.MH6 U1.A3 U1.A4 U1.A5 U1.A6 U1.A7 U1.A8 U1.A9 U1.A10 U1.A13 U1.A14 U1.A15 U1.A16 U1.A17 U1.A18 U1.A19 U1.A20 U1.AB3 U1.AB4 U1.AB5 U1.AB6 U1.AB17 U1.AB18 U1.AB19 U1.AB20 U1.C18 U1.C19 U1.Y19 U2.1 U2.5 U2.9 U2.13 U2.16 U5.1 U6.11 U8.2

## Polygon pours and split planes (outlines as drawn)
VCCIN on Top Layer "Top Layer-VCCIN" (solid, remove dead copper, pour order 1000): 50.8,15.1 69,15.1 69,21.6 50.8,21.6
VCCRIO on Top Layer "Top Layer-VCCRIO" (solid, remove dead copper, pour order 1001): 53.2,78.1 58.4,72.9 56,70.5 56,65.2 37.8,47 32,52.8 29.8,55
GND on Top Layer "Top Layer-GND" (solid, remove dead copper, pour order 1002): 0,99.5 69,99.5 69,0 0,0
VCC on Top Layer "Top Layer-VCC" (solid, remove dead copper, pour order 1003): 0,99.5 0,53 23,53 23,99.5
GND on MidLayer1 "MidLayer1-GND" (solid, remove dead copper, pour order 1004): 0,99.5 69,99.5 69,0 0,0
VCCAUX on MidLayer1 "MidLayer1-VCCAUX" (solid, remove dead copper, pour order 1005): 36.1,31.5 36.1,0 57.1,0 57.1,31.5
GND on MidLayer2 "MidLayer2-GND" (solid, remove dead copper, pour order 1006): 0,99.5 69,99.5 69,0 0,0
GND on MidLayer3 "MidLayer3-GND" (solid, remove dead copper, pour order 1007): 0,99.5 69,99.5 69,0 0,0
VCCIN on MidLayer3 "MidLayer3-VCCIN" (solid, remove dead copper, pour order 1008): 25.5,82.7 25.5,67.1 31.5,67.1 37.4,73 60.2,73 60.2,16.6 68.7,16.6 68.7,82.5 26.8,82.5
VCCAUX on MidLayer3 "MidLayer3-VCCAUX" (solid, remove dead copper, pour order 1009): 13.5,50.3 21.3,50.3 21.3,23 13.6,23 13.6,50.3
VCCAUX on MidLayer3 "MidLayer3-VCCAUX 1" (solid, remove dead copper, pour order 1010): 44.9,60.7 44.9,5.6 55.1,5.6 61,11.5 61,60.5 44.9,60.5
GND on MidLayer4 "MidLayer4-GND" (solid, remove dead copper, pour order 1011): 0,99.5 69,99.5 69,0 0,0
VCCINT on MidLayer4 "MidLayer4-VCCINT" (solid, remove dead copper, pour order 1012): 7.4,60.4 54.2,60.4 54.2,29.5 7.487,29.5
GND on Bottom Layer "Bottom Layer-GND" (solid, remove dead copper, pour order 1013): 0,99.7 69,99.7 69,0 0,0
VCCINT on Bottom Layer "Bottom Layer-VCCINT" (solid, remove dead copper, pour order 1014): 0,56.4 69,56.4 69,21.3 0,21.3
VCC on Bottom Layer "Bottom Layer-VCC" (solid, remove dead copper, pour order 1015): 0,99.6 35,99.6 35,50.1 0,50.1
GND on InternalPlane1 (split plane): 36.23,98.49 37.96,98.46 39.69,98.41 41.418,98.34 43.146,98.251 44.873,98.141 46.598,98.011 48.322,97.861 50.044,97.692 51.764,97.502 53.481,97.293 55.196,97.064 56.908,96.815 58.617,96.546 60.323,96.258 62.026,95.95 63.725,95.622 65.42,95.275 67.11,94.908 67.998,94.704 67.999,1.001 1.001,1.001 1.002,94.704 1.89,94.908 3.58,95.275 5.275,95.622 6.974,95.95 8.677,96.258 10.383,96.546 12.092,96.815 13.804,97.064 15.519,97.293 17.236,97.502 18.956,97.692 20.678,97.861 22.402,98.011 24.127,98.141 25.854,98.251 27.582,98.34 29.31,98.41 31.04,98.46 32.77,98.49 34.5,98.5
VCC on InternalPlane2 (split plane): 36.23,98.49 37.96,98.46 39.69,98.41 41.418,98.34 43.146,98.251 44.873,98.141 46.598,98.011 48.322,97.861 50.044,97.692 51.764,97.502 53.481,97.293 55.196,97.064 56.908,96.815 58.617,96.546 60.323,96.258 62.026,95.95 63.725,95.622 65.42,95.275 67.11,94.908 67.998,94.704 67.999,1.001 1.001,1.001 1.002,94.704 1.89,94.908 3.58,95.275 5.275,95.622 6.974,95.95 8.677,96.258 10.383,96.546 12.092,96.815 13.804,97.064 15.519,97.293 17.236,97.502 18.956,97.692 20.678,97.861 22.402,98.011 24.127,98.141 25.854,98.251 27.582,98.34 29.31,98.41 31.04,98.46 32.77,98.49 34.5,98.5

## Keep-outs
Top Layer:
  circle w0.254: c50.7,12.6 r3.306
  circle w0.254: c4.3,21.3 r3.306
  circle w0.254: c22.1,64.5 r3.306
Bottom Layer:
  circle w0.254: c39.2,85.6 r3.324
  circle w0.254: c56.1,35.1 r3
  circle w0.254: c8.9,20.8 r3
  rectangle: 53.6,85.8 58.6,88.2
Keep-Out Layer:
  lines w0.2: 0.8,0.8 0.8,86.942 cw(c2,88) 0.8,89.058 0.8,91.942 cw(c2,93) 0.8,94.058 0.8,94.865 cw(c34.5,-51.301) 68.2,94.865 68.2,90.558 cw(c67,89.5) 68.2,88.442 68.2,85.558 cw(c67,84.5) 68.2,83.442 68.2,0.8 0.8,0.8
Mechanical 7:
  lines w0.2: 53.545,85.751 53.545,88.291 58.625,88.291 58.625,85.751 53.545,85.751

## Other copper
Top Layer:
  rectangle net VCCINT: 50.7,51.2 51.9,56.9
  rectangle net VCCAUX: 51.5,57.9 52.8,59.6
  rectangle net VCCINT: 51.9,49.2 52.7,50
  rectangle net VCCINT: 48.9,46.1 52.3,52.7
  rectangle net GND: 64.2,41.2 67.8,46.7
  rectangle net NetL1_1: 58.2,42.453 61.8,45.4
  rectangle net GND: 64.2,40.6 65.3,41.7
  rectangle net NetL1_1: 58.7,41.7 61.2,43
  rectangle net 5V: 53.3,42.3 55.7,47.8
  rectangle net VCCINT: 51.3,48.2 54,52.7
  rectangle net VCCINT: 51.1,45.6 53,48.5
  rectangle net GND: 56.2,45.7 60.5,57.7
  rectangle net GND: 57.3,45.7 67.7,53.5
  rectangle net 5V: 52.1,42.1 55.7,44.7
Bottom Layer:
  rectangle net VCCIN: 56,69.2 57.6,72.3
  rectangle net VCCIN: 54.9,70.4 57.7,72.4
  rectangle net VCCIN: 54.8,72 60.3,74.3
  rectangle net NetL1_1: 58.5,41.7 61.6,45.1
  rectangle net NetL1_1: 59.3,48.2 63.1,51.8
  rectangle net VCCAUX: 51.5,57.7 52.7,59.4
  rectangle net GND: 54.6,66.9 55.5,69.3
  rectangle net GND: 53.1,68.5 55.5,69.3
  rectangle net VCCINT: 46.5,47 53.9,52
  rectangle net 5V: 53.1,58 55,59.4
  rectangle net VCC: 12,72 15.7,81.6
  rectangle net VCC: 3,70.9 13.6,82.1
  rectangle net 5V: 52.9,42.2 55.8,44.5
  rectangle net VCCRIO: 49.8,73.4 51.1,74.5
  rectangle net GND: 53.3,18 54.9,20
  rectangle net VCCIN: 51.2,18.6 52.4,20.7

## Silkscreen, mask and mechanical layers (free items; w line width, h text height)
Top Overlay:
  lines w0.08: 13,1.1 14,1.4 ; 13.9,22 14.8,21.5 ; 16.1,6.8 16.1,8.6 ; 19.3,6.9 19.3,8.4 ; 23.9,7.4 23.9,8.5 ; 28.1,6.7 28.1,8.4 ; 30.7,77.6 31.2,78.3 ; 38.4,79.3 39.2,79.7 ; 40.8,77.6 41.6,78.7 ; 43.1,8.2 44.1,6.6 ; 44.1,76 45.5,75.2 ; 47.8,78.9 48.5,78.8 ; 47.9,6.9 47.9,8.2 ; 53.7,6.5 54.2,8.4 ; 57.9,46.6 58.9,46.6 ; 65.9,20.7 66.2,21.8
  lines w0.2: 8.1,91.2 9.9,94.1 ; 14.1,91 14.1,91.8 ; 15.7,94.9 18.4,93.7 ; 30.6,92 30.6,92.7 ; 32.3,96 35.5,93.9 ; 47,91.5 47,92.2 ; 49.5,95.3 52.5,92.7 ; 64.4,90.5 64.4,91.2
  text "RX1N" at 29.7,96.4 h1.4
  text "TX1P" at 46.8,95.7 h1.4
  text "TX0P" at 12.7,95.4 h1.4
  text "RX0N" at 7.2,94.6 h1.4
  text "TX0N" at 28,93.1 h1.4
  text "RX1P" at 44.6,92.6 h1.4
  text "RX0P" at 11.5,92.2 h1.4
  text "TX1N" at 61.8,91.6 h1.4
Bottom Overlay:
  drawing of 857 lines, arcs and shapes, not listed
  text "1" at 13.97,58.42 h1.2
  text "1" at 14.224,7.62 h1.2
  text "REV 1.01" at 36.5,2.7 h1.3
  text "NBP8" at 42.7,2.7 h1.3
PCB Boundary:
  lines w0.2: 0,0 0.001,95.5 cw(c34.5,-51.301) 68.999,95.5 69,0 0,0
  text "PCB boundary coincides with centre-line of tracks and arc" at 0,-12 h0.75
Gerber ID:
  text ".Layer_Name" at 0,-6 h0.75
Printout ID:
  text ".Printout_Name" at 0,-10 h0.75
Mechanical 5:
  circle w0.254: c64.5,87 r8
  circle w0.254: c56,92.5 r8
  circle w0.254: c39,94 r8
  circle w0.254: c47,88 r8
  circle w0.254: c22,93.5 r8
  circle w0.254: c30.5,88.5 r8
  circle w0.254: c14,87.5 r8
  circle w0.254: c4.5,90.5 r8
  circle w0.254: c4.5,90.5 r4.7
  circle w0.254: c14,87.5 r4.7
  circle w0.254: c22,93.5 r4.7
  circle w0.254: c30.5,88.5 r4.7
  circle w0.254: c39,94 r4.7
  circle w0.254: c56,92.5 r4.7
  circle w0.254: c47,88 r4.7
  circle w0.254: c64.5,87 r4.7
Mechanical 7:
  circle w0.2: c57.355,87.021 r0.6
  circle w0.2: c54.815,87.021 r0.6
  lines w0.2: 0.001,77 cw(c34.5,-69.801) 68.999,77 ; 0.001,79.5 cw(c34.5,-67.301) 68.999,79.5 ; 0,0 0.001,95.5 cw(c34.5,-51.301) 68.999,95.5 69,0 0,0
Design Information:
  drawing of 719 lines, arcs and shapes, not listed
  text "NBP8 REV 1.01" at 317.627,202.041 h1.27
  text "DESIGN INFORMATION" at 261.62,201.914 h1.52
  text "BOARD NAME:" at 299.212,201.914 h1.52
  text "BOARD TECHNOLOGY" at 261.62,199.374 h1.52
  text "BOARD SIZE (REFER ALSO PROFILING INFORMATION)" at 309.88,199.374 h1.27
  text "69.00mm" at 312.6,197.1 h1.52
  text "15.000" at 277.419,197.012 h1.52
  text "99.50mm" at 335.6,197 h1.52
  text "5.000" at 291.389,196.885 h1.52
  text "5" at 266.446,196.834 h1.52
  text "X" at 328.549,196.326 h1.78
  text "(MIN. TRACK/   PADS  /   CLEARANCE     IN 0.001'')" at 260.096,194.294 h1.27
  text "MINIMUM ANNULAR RING 0.05MM (0.002'') EXTERNAL PER IPC-2221 CLASS 3 LEVEL C AND IS THE" at 261.62,191.754 h1.27
  text "MANUFACTURING REGISTRATION ALLOWANCE" at 261.62,189.468 h1.27
  text "LAND SIZE CALCULATION MINIMUM - NOMINAL HOLE SIZE + 0.508MM (0.020'')" at 261.62,186.674 h1.27
  text "AS INSTRUCTED" at 347.65,182.28 h1.52
  text "X" at 299.263,182.153 h1.52
  text "CIRCUIT TYPE:" at 261.62,182.102 h1.52
  text "SS" at 284.48,182.102 h1.27
  text "DS" at 302.26,182.102 h1.27
  text "X" at 316.865,182.102 h1.52
  text "PTH" at 320.04,182.102 h1.27
  text "ML" at 330.962,182.102 h1.27
  text "X" at 334.772,182.102 h1.52
  text "No. OFF" at 337.82,182.102 h1.27
  text "FINGER CONNECTOR DIM PER:" at 261.62,179.054 h1.52
  text "AS SHOWN" at 337.82,179.054 h1.27
  text "No. OFF TOTAL" at 278.384,176.26 h1.52
  text "ONE SIDE" at 320.04,176.26 h1.27
  text "BOTH SIDES" at 337.82,176.006 h1.27
  text "VIAS:" at 261.62,173.339 h1.52
  text "NONE" at 273.05,173.339 h1.14
  text "X" at 281.432,173.339 h1.52
  text "FEED THRU'" at 284.48,173.339 h1.14
  text "X" at 299.212,173.339 h1.52
  text "TENTED" at 302.26,173.339 h1.14
  text "BURIED LAYER SEQUENCE" at 320.04,173.339 h1.14
  text "UNIQUE DRILL" at 284.48,170.291 h1.14
  text "2 SIZE" at 302.26,170.291 h1.14
  text "BLIND LAYER SEQUENCE" at 320.04,170.291 h1.14
  text "Layer Stack Manager (Protel)" at 297.053,168.005 h1.27
  text "X" at 334.772,168.005 h1.52
  text "AS SHOWN" at 337.82,168.005 h1.27
  text "LAYER CONSTRUCTION PER:" at 261.62,167.878 h1.52
  text "Protel" at 342.646,165.338 h1.27
  text "(PFW)" at 352.933,165.211 h1.27
  text "ARTWORK:" at 261.62,165.084 h1.52
  text "MANUAL" at 284.48,165.084 h1.27
  text "DIGITISED" at 302.26,165.084 h1.27
  text "X" at 316.992,165.084 h1.52
  text "CAD" at 320.04,165.084 h1.27
  text "TYPE" at 330.962,165.084 h1.27
  text "ARTWORK/PATTERN MASTER LIST" at 261.62,160.385 h1.52
  text "DESCRIPTION" at 262.89,157.972 h1.27
  text "DRAWING No./CAD FILE REF." at 281.559,157.972 h1.27
  text "LAYER NAME" at 322.834,157.972 h1.27
  text "GERBER FILE REF" at 343.586,157.896 h1.27
  text "PCB FILE" at 261.366,155.432 h1.27
  text "BOCD_Virtex_II_Pro_FG456" at 281.737,155.356 h1.27
  text "PcbDoc" at 312.979,155.356 h1.02
  text "Top Paste Mask" at 321.158,152.892 h1.02
  text "GTP" at 363.779,152.816 h1.27
  text "GERBER FILE" at 261.366,152.765 h1.27
  text "GTO" at 363.728,150.327 h1.27
  text "Top Overlay" at 321.158,150.301 h1.02
  text "GERBER FILE" at 261.366,150.225 h1.27
  text "Top Solder Mask" at 321.158,147.863 h1.02
  text "GTS" at 363.779,147.736 h1.27
  text "GERBER FILE" at 261.366,147.685 h1.27
  text "TOP LAYER" at 321.158,145.272 h1.02
  text "GTL" at 363.779,145.196 h1.27
  text "GERBER FILE" at 261.366,145.145 h1.27
  text "INTERNALPLANE1" at 321.158,142.732 h1.02
  text "GP1" at 363.779,142.656 h1.27
  text "GERBER FILE" at 261.366,142.605 h1.27
  text "INTERNALPLANE2" at 321.158,140.192 h1.02
  text "GP2" at 363.728,140.167 h1.27
  text "GERBER FILE" at 261.366,140.065 h1.27
  text "G1" at 363.728,137.754 h1.27
  text "MIDLAYER1" at 321.158,137.652 h1.02
  text "GERBER FILE" at 261.366,137.525 h1.27
  text "MIDLAYER2" at 321.158,135.112 h1.02
  text "G2" at 363.728,135.087 h1.27
  text "GERBER FILE" at 261.366,134.985 h1.27
  text "MIDLAYER3" at 321.158,132.572 h1.02
  text "G3" at 363.779,132.496 h1.27
  text "GERBER FILE" at 261.366,132.445 h1.27
  text "MIDLAYER4" at 321.158,130.032 h1.02
  text "G4" at 363.728,130.007 h1.27
  text "GERBER FILE" at 261.366,129.905 h1.27
  text "BOTTOMLAYER" at 321.158,127.492 h1.02
  text "GBL" at 363.779,127.416 h1.27
  text "GERBER FILE" at 261.366,127.365 h1.27
  text "Bottom Solder Mask" at 321.158,125.003 h1.02
  text "GBS" at 363.779,124.876 h1.27
  text "GERBER FILE" at 261.366,124.825 h1.27
  text "Bottom Overlay" at 321.158,122.412 h1.02
  text "GBO" at 363.779,122.336 h1.27
  text "GERBER FILE" at 261.366,122.285 h1.27
  text "Bottom Paste Mask" at 321.158,119.923 h1.02
  text "GBP" at 363.779,119.796 h1.27
  text "GERBER FILE" at 261.366,119.745 h1.27
  text "PCB Boundary" at 321.158,117.332 h1.02
  text "GM1" at 363.779,117.256 h1.27
  text "GERBER FILE" at 261.366,117.205 h1.27
  text "APERTURE LIST" at 261.366,114.792 h1.27
  text "APR" at 313.979,114.716 h1.27
  text "DRILL REPORT" at 261.366,112.252 h1.27
  text "DRR" at 313.979,112.176 h1.27
  text "EXCELLON DRILL" at 261.366,109.712 h1.27
  text "TXT" at 313.979,109.636 h1.27
  text "MATERIAL:" at 261.62,99.298 h1.52
  text "GLASS FIBRE EPOXY RESIN NEMA GRADE FR4 (MIL-S-13949H)" at 287.274,99.044 h1.27
  text "X" at 284.607,98.917 h1.52
  text "THICKNESS:" at 269.494,96.123 h1.27
  text "0.8mm" at 287.274,96.123 h1.27
  text "1.2mm" at 304.927,96.123 h1.27
  text "1.6mm" at 322.58,96.123 h1.27
  text "2.4mm" at 340.36,96.123 h1.27
  text "3.2mm" at 358.14,96.123 h1.27
  text "X" at 320.167,95.996 h1.52
  text "TOLERANCE:" at 269.367,93.075 h1.27
  text "IN A/W IPC-D-300G CLASS" at 287.02,93.075 h1.27
  text "3 LEVEL B" at 321.945,93.075 h1.27
  text "OTHER +/-" at 340.36,93.075 h1.27
  text "X" at 284.607,92.948 h1.52
  text "BOW & TWIST:" at 266.954,90.027 h1.27
  text "IN A/W IPC-D-300G CLASS" at 287.02,90.027 h1.27
  text "3 LEVEL B" at 321.945,90.027 h1.27
  text "AS SHOWN" at 340.487,89.9 h1.27
  text "X" at 284.607,89.773 h1.52
  text "COPPER THICKNESS (FINISHED)" at 269.367,86.725 h1.27
  text "OUTER:" at 274.193,84.439 h1.27
  text "18um" at 287.274,84.439 h1.27
  text "35um" at 314.325,84.439 h1.27
  text "70um" at 340.614,84.439 h1.27
  text "X" at 311.582,84.236 h1.52
  text "INNER SIGNAL:" at 265.811,81.391 h1.27
  text "18um" at 287.274,81.391 h1.27
  text "35um" at 314.325,81.391 h1.27
  text "70um" at 340.614,81.391 h1.27
  text "X" at 311.531,81.188 h1.52
  text "INNER PWR:" at 269.494,78.343 h1.27
  text "18um" at 287.274,78.343 h1.27
  text "35um" at 314.325,78.343 h1.27
  text "70um" at 340.614,78.343 h1.27
  text "X" at 311.658,78.216 h1.52
  text "STRUCTURE:" at 261.62,75.295 h1.52
  text "REFER" at 287.274,75.295 h1.27
  text "AS PER DRAWING No." at 287.147,72.12 h1.27
  text "AS SHOWN" at 340.487,72.12 h1.27
  text "X" at 337.947,71.993 h1.52
  text "DRILLING:" at 261.62,69.326 h1.52
  text "VIEWED FROM:" at 266.573,67.04 h1.27
  text "COMPONENT SIDE" at 287.274,67.04 h1.14
  text "SOLDER SIDE" at 314.071,67.04 h1.14
  text "X" at 284.607,66.786 h1.52
  text "REFERENCE:" at 268.859,63.992 h1.27
  text "AS SHOWN" at 287.147,63.865 h1.14
  text "PATTERN MASTER LIST" at 314.198,63.865 h1.14
  text "X" at 337.947,63.865 h1.52
  text "NC_DRILL FILES" at 340.487,63.865 h1.14
  text "X" at 284.607,63.738 h1.52
  text "PTH MINIMUM COPPER THICKNESS:" at 274.701,60.944 h1.27
  text "20um" at 314.325,60.944 h1.27
  text "X" at 311.658,60.817 h1.52
  text "OTHER" at 340.487,60.817 h1.27
  text "NPTH:" at 275.209,57.896 h1.27
  text "TENTED" at 287.147,57.769 h1.14
  text "X" at 311.658,57.769 h1.52
  text "PADS REMOVED" at 314.198,57.769 h1.14
  text "REMOVE PADS" at 340.487,57.769 h1.14
  text "X" at 284.607,57.642 h1.52
  text "2nd DRILL" at 287.147,54.721 h1.14
  text "BOTH" at 314.198,54.721 h1.14
  text "AS SHOWN" at 326.517,54.721 h1.14
  text "NONE" at 340.487,54.721 h1.14
  text "BOARD FINISH:" at 261.62,51.8 h1.52
  text "X" at 284.607,51.673 h1.52
  text "ETCHING" at 287.147,51.673 h1.14
  text "REFER PATTERN MASTER LIST" at 314.198,51.673 h1.14
  text "LEGEND / SCREEN PRINT:" at 281.94,48.752 h1.27
  text "NONE" at 314.198,48.625 h1.14
  text "COMPONENT" at 326.517,48.625 h1.14
  text "SOLDER" at 340.487,48.625 h1.14
  text "X" at 323.977,48.498 h1.52
  text "X" at 337.947,48.498 h1.52
  text "COLOUR:" at 272.161,45.704 h1.27
  text "WHITE" at 287.147,45.577 h1.14
  text "YELLOW" at 314.198,45.577 h1.14
  text "OTHER" at 340.487,45.577 h1.14
  text "X" at 284.607,45.45 h1.52
  text "X" at 284.607,42.529 h1.52
  text "LIQUID PHOTOIMAGEABLE" at 287.147,42.529 h1.14
  text "SCREEN PRINT" at 326.517,42.529 h1.14
  text "MATTE" at 287.147,39.481 h1.14
  text "GLOSS" at 299.847,39.481 h1.14
  text "GREEN" at 314.198,39.481 h1.14
  text "BLUE" at 326.517,39.481 h1.14
  text "G/Y" at 340.487,39.481 h1.14
  text "OTHER" at 351.917,39.481 h1.14
  text "X" at 297.18,39.354 h1.52
  text "SOLDER MASK COLOUR:" at 261.62,36.56 h1.14
  text "BLACK" at 287.147,36.433 h1.14
  text "GREEN" at 299.847,36.433 h1.14
  text "YELLOW" at 314.198,36.433 h1.14
  text "BLUE" at 326.517,36.433 h1.14
  text "OTHER" at 340.487,36.433 h1.14
  text "X" at 284.48,36.306 h1.52
  text "TRACK FINISH:" at 261.62,33.512 h1.52
  text "X" at 284.607,33.385 h1.52
  text "SELECTIVE SOLDER (HASL)" at 287.147,33.385 h1.14
  text "REFLOW SOLDER" at 326.517,33.385 h1.14
  text "SELECTIVE GOLD" at 287.147,30.337 h1.14
  text "um  (AREA" at 314.198,30.337 h1.14
  text "sq. mm)" at 342.011,30.337 h1.14
  text "REFER PATTERN MASTER LIST" at 287.147,27.289 h1.14
  text "OTHER" at 326.517,27.289 h1.14
  text "EDGE BOARD" at 261.62,24.368 h1.52
  text "1.3um HARD GOLD OVER 5um     NICKEL / TIN-NICKEL" at 287.147,24.241 h1.14
  text "CONTACTS:" at 261.62,22.209 h1.52
  text "HARD FINISH GOLDE PLATE" at 287.147,21.193 h1.14
  text "OTHER" at 326.517,21.193 h1.14
  text "AS SHOWN" at 287.147,18.145 h1.14
  text "REFER" at 326.517,18.145 h1.14
  text "PROFILING:" at 261.62,15.097 h1.52
  text "AS DIMENSIONED, MEASURED AND CUT FROM SPECIFIED DATUM." at 287.147,15.097 h1.14
  text "X" at 284.607,14.97 h1.52
  text "REFER PCB BLANK DWG No." at 287.274,12.176 h1.27
  text "USE PROFILE / ROUTE TAPE SUPPLIED (REFER PATTERN MASTER LIST)" at 287.274,9.128 h1.27
  text "SQUARE CUT" at 287.274,6.08 h1.27
  text "N.C. ROUTE" at 305.054,6.08 h1.27
  text "V. SCORE" at 322.834,6.08 h1.27
  text "BLANK" at 340.614,6.08 h1.27
  text "ACCEPTABILITY:" at 261.62,3.413 h1.52
  text "MATERIALS AND WORKMANSHIP FOR ALL PRINTED WIRING BOARDS TO MEET" at 283.845,3.286 h1.27
  text "OR EXCEED THE REQUIREMENTS OF:" at 283.845,0.492 h1.27
  text "IPC-6011/12 AND IPC-A-600E" at 287.401,-2.175 h1.27
  text "1" at 322.961,-2.175 h1.27
  text "2" at 331.851,-2.175 h1.27
  text "X" at 329.184,-2.302 h1.52
  text "X" at 284.734,-2.429 h1.52
  text "3" at 340.741,-4.334 h1.27
  text "UL CERTIFICATION" at 287.401,-5.223 h1.27
  text "AUSTEL" at 322.961,-5.223 h1.27
  text "X" at 284.734,-5.35 h1.52
  text "ML-P-55110F GRP" at 286.893,-8.271 h1.02
  text "A" at 305.181,-8.271 h1.27
  text "B" at 314.071,-8.271 h1.27
  text "AS2546" at 322.961,-8.271 h1.27
  text "OTHER" at 340.741,-8.271 h1.27
  text "ADDITIONAL" at 261.62,-11.192 h1.52
  text "NONE" at 287.401,-11.446 h1.27
  text "SAMPLE PLAN" at 305.181,-11.446 h1.27
  text "MIL-P-55110E SERIAL Nos. PER ORDER" at 322.961,-11.446 h1.27
  text "REQUIREMENTS:" at 261.62,-13.605 h1.52
  text "NONE" at 287.401,-14.494 h1.27
  text "ML-P-55110F GRP" at 304.673,-14.494 h1.02
  text "A" at 322.961,-14.494 h1.27
  text "B" at 331.851,-14.494 h1.27
  text "IPC CLASS:" at 337.82,-14.494 h1.27
  text "1" at 353.314,-14.494 h1.27
  text "2" at 359.664,-14.494 h1.27
  text "3" at 366.014,-14.494 h1.27
  text "QUALITY RELEASE REPORT" at 305.181,-17.542 h1.27
  text "OTHER" at 345.694,-17.542 h1.27
  text "PER ORDER" at 354.203,-17.669 h1.27
  text "X" at 343.027,-17.796 h1.52
  text "NONE" at 305.181,-20.59 h1.27
  text "REQUIRED" at 322.961,-20.59 h1.27
  text "PER ORDER" at 345.821,-20.59 h1.27
  text "ELECTRICAL TEST:" at 261.62,-20.717 h1.52
  text "X" at 320.294,-20.717 h1.52
  text "NONE" at 305.181,-23.638 h1.27
  text "1 SIDE" at 322.834,-23.638 h1.14
  text "2 SIDES" at 334.01,-23.638 h1.14
  text "MIN. PITCH" at 345.694,-23.638 h1.27
  text "0.65mm" at 359.283,-23.638 h1.27
  text "SURFACE MOUNT:" at 261.62,-23.765 h1.52
  text "X" at 331.775,-23.841 h1.52
  text "NONE" at 305.181,-26.686 h1.27
  text "FOIL" at 322.961,-26.686 h1.27
  text "LEGEND" at 334.391,-26.686 h1.27
  text "REFER" at 345.694,-26.686 h1.27
  text "MANUFACTURER'S ID/LOGO:" at 261.62,-26.813 h1.52
  text "X" at 302.514,-26.94 h1.52
  text "ISO9001/AS3901" at 308.991,-29.734 h1.27
  text "NONE" at 345.694,-29.734 h1.27
  text "MANUFACTURER'S ACCREDITATION:" at 261.62,-29.861 h1.52
  text "X" at 306.324,-29.861 h1.52
  text "PER ORDER" at 305.181,-32.782 h1.27
  text "REFER" at 322.961,-32.782 h1.27
  text "PACKAGING AND HANDLING:" at 261.62,-32.909 h1.52
  text "X" at 302.514,-33.036 h1.52
Sheet:
  drawing of 1882 lines, arcs and shapes, not listed
  text "1" at 3.717,207.391 h1.78
  text "2" at 52.756,207.391 h1.78
  text "3" at 102.015,207.391 h1.78
  text "4" at 151.308,207.391 h1.78
  text "5" at 200.584,207.391 h1.78
  text "6" at 249.606,207.391 h1.78
  text "7" at 299.136,207.391 h1.78
  text "8" at 348.158,207.391 h1.78
  text "A" at -18.415,173.406 h1.78
  text "A" at 370.205,173.406 h1.78
  text "B" at -18.415,102.794 h1.78
  text "B" at 370.205,102.794 h1.78
  text "C" at -18.415,32.182 h1.78
  text "C" at 370.205,32.182 h1.78
  text "D" at -18.415,-37.922 h1.78
  text "D" at 370.205,-37.922 h1.78
  text "ENGINEER:" at 255.27,-38.1 h1.14
  text "TITLE:" at 293.37,-38.1 h1.14
  text "PCB DESIGNER:" at 255.27,-45.593 h1.14
  text "DATE:" at 255.27,-53.34 h1.14
  text "PART NO.:" at 293.37,-53.34 h1.14
  text "REV:" at 346.71,-53.34 h1.14
  text "Altium Limited" at 222.25,-55.88 h1.78
  text ".PRINT_DATE" at 256.54,-56.388 h1.78
  text "12a Rodborough Rd" at 222.25,-58.42 h1.78
  text "Frenchs Forest" at 222.25,-60.96 h1.78
  text "FILE NAME:" at 255.27,-60.96 h1.14
  text "DWG NO:" at 293.37,-60.96 h1.14
  text "SCALE:" at 346.71,-60.96 h1.14
  text "NSW 2086" at 222.25,-63.5 h1.78
  text ".PCB_FILE_NAME_NO_PATH" at 256.54,-64.008 h1.78
  text "1" at 3.717,-69.469 h1.78
  text "2" at 52.756,-69.469 h1.78
  text "3" at 102.015,-69.469 h1.78
  text "4" at 151.308,-69.469 h1.78
  text "5" at 200.584,-69.469 h1.78
  text "6" at 249.606,-69.469 h1.78
  text "7" at 299.136,-69.469 h1.78
  text "8" at 348.158,-69.469 h1.78
Drill Drawing:
  text ".Legend" at 0,-8 h0.75

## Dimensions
34.5,-51.301 to 36.6,102 on Dimensions
0,0 to 69,0 on Dimensions
0,0 to 0.001,95.5 on Dimensions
